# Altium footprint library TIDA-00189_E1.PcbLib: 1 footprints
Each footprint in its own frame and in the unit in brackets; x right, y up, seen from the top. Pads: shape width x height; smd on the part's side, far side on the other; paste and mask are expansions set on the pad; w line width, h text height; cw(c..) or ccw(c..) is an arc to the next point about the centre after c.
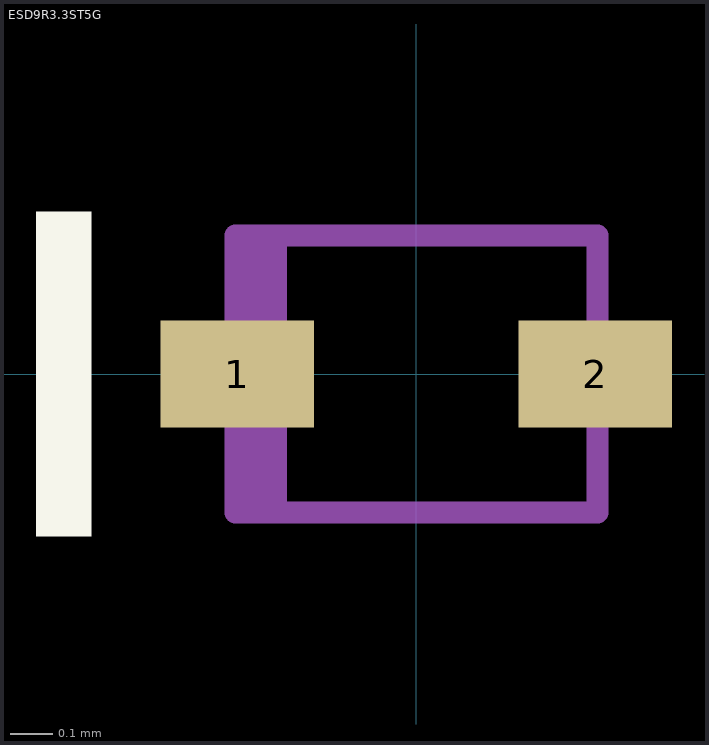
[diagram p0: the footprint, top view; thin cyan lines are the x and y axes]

## ESD9R3.3ST5G [mm] "TVS DIODE 3.3VWM 7.8VC SOD923"
height 0.4
pads (2):
  rect 0.36x0.25 smd: 1(-0.42,0) 2(0.42,0)
Top Overlay:
  rectangle: -0.893,-0.381 -0.762,0.381
M5 Assembly Top:
  rectangle: -0.426,-0.325 -0.304,0.325
  lines w0.051: -0.425,-0.325 -0.425,0.325 0.425,0.325 0.425,-0.325 -0.425,-0.325
  text ".Designator" at -0.244,-0.057 h0.15
3D body: height 0.4, standoff 0.4, extent -0.299,-0.324 -0.151,0.324
3D body: height 0.4, standoff 0, extent -0.445,-0.345 0.445,0.345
